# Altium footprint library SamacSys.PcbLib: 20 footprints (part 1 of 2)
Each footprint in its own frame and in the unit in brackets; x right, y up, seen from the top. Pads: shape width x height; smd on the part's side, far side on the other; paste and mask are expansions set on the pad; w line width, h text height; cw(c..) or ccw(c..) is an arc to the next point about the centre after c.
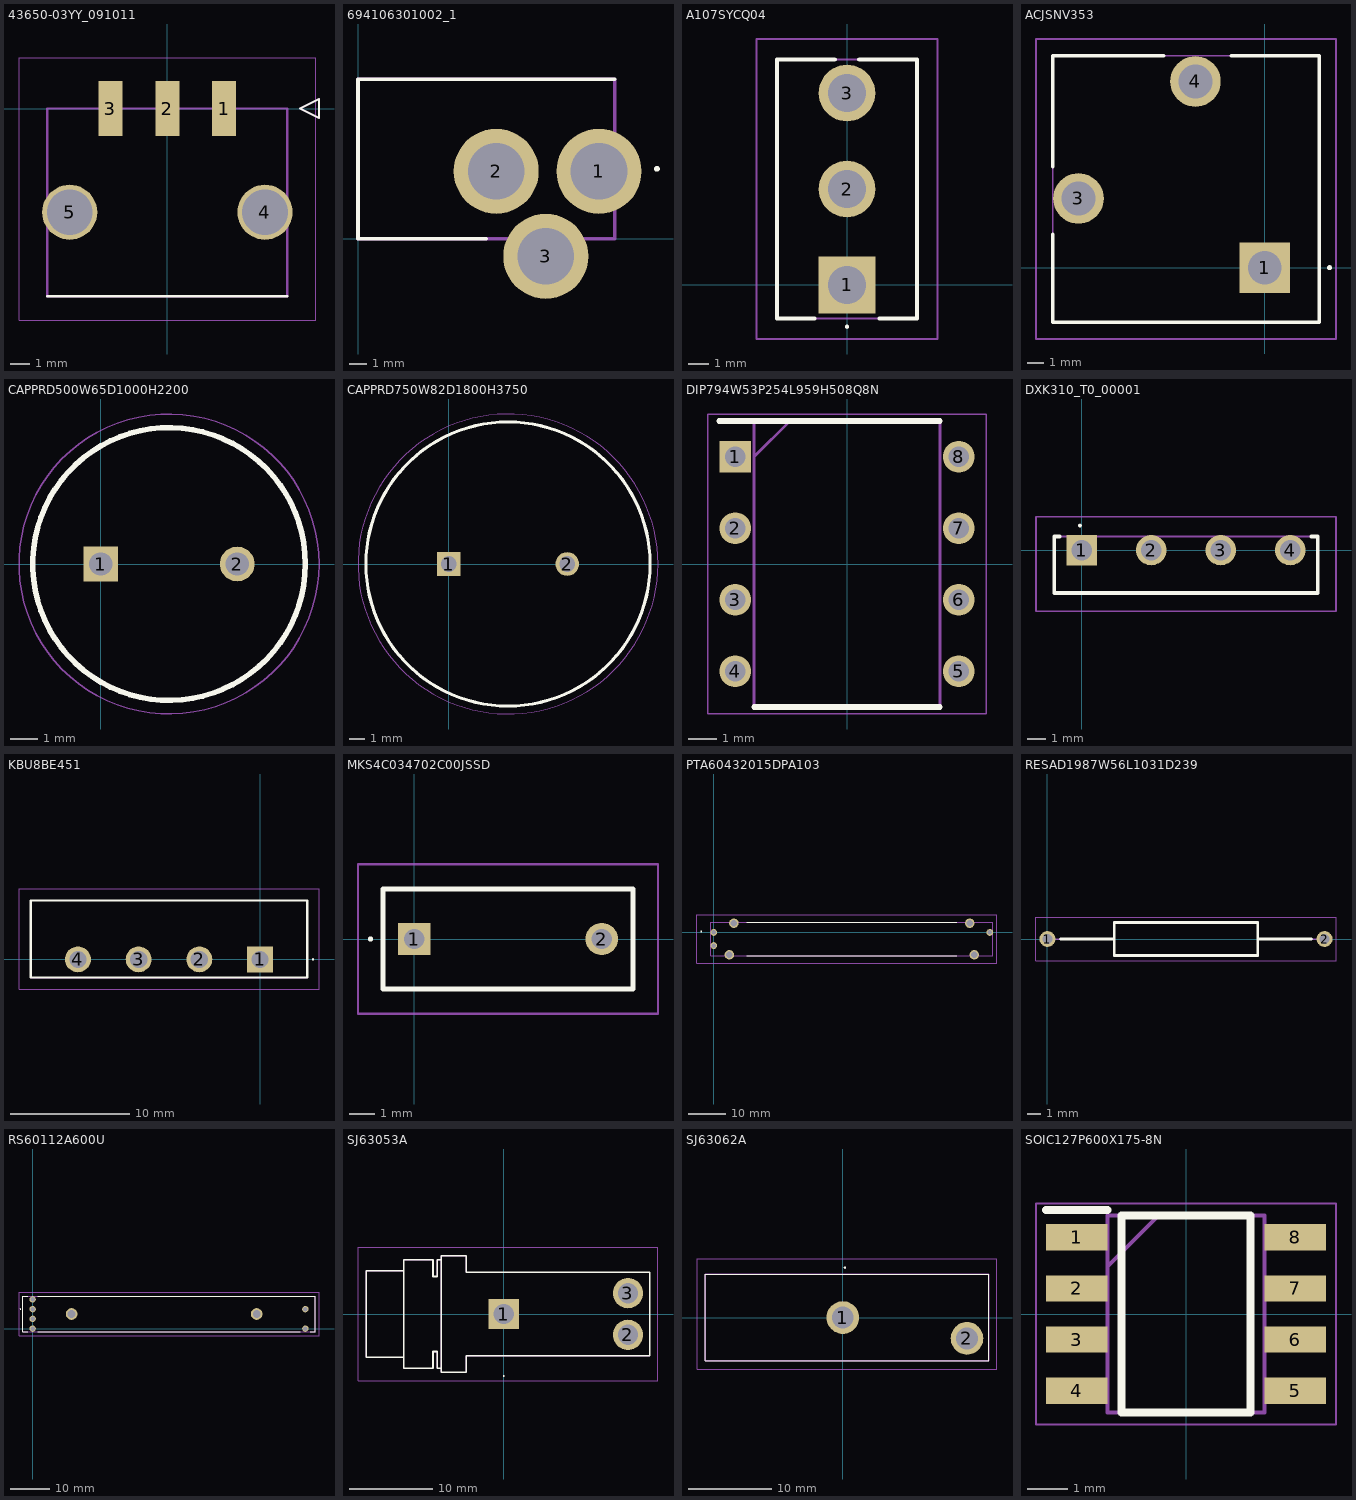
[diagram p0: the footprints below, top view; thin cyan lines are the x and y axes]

## 43650-03YY_091011 [mm]
pads (5):
  rect 1.27x2.92 smd: 1(3,0) 2(0,0) 3(-3,0)
  round 2.91 hole 2.41: 4(5.15,-5.47) 5(-5.15,-5.47)
Top Overlay:
  lines w0.127: -6.325,-9.9 6.325,-9.9 ; 7,0 8,0.5 8,-0.5 7,0
Mechanical 13:
  lines w0.127: -6.325,-9.9 -6.325,0 6.325,0 6.325,-9.9 -6.325,-9.9 ; 7,0 8,0.5 8,-0.5 7,0
Mechanical 15:
  lines w0.05: -7.824,-11.17 -7.824,2.679 7.824,2.679 7.824,-11.17 -7.824,-11.17
3D body "43650-0310.stp": height 5.71, standoff -1.9, extent -6.175,-10.06 6.475,0.678

## 694106301002_1 [mm]
pads (3):
  round 4.8 hole 3.2: 1(13.6,3.8) 2(7.8,3.8) 3(10.6,-1)
Top Overlay:
  circle w0.2: c16.867,3.939 r0.064
  lines w0.2: 7.25,0 0,0 0,9 14.5,9
Mechanical 13:
  lines w0.2: 0,0 0,9 14.5,9 14.5,0 0,0
3D body "694106301002.stp": height 11.02, standoff -3.47, extent 0.12,-1.22 14.62,8.28

## A107SYCQ04 [mil]
pads (3):
  rect 109.49x109.49 hole 73: 1(0,0)
  round 109.49 hole 73: 2(0,185) 3(0,370)
Top Overlay:
  lines w3.94: 0,-82.68 ccw(c0,-80.71) 0,-78.74 ccw(c0,-80.71) 0,-82.68
  lines w7.87: -62.99,-65 -135,-65 -135,435 -23.62,435 ; 23.62,435 135,435 135,-65 62.99,-65
Mechanical 13:
  lines w3.94: -135,-65 -135,435 135,435 135,-65 -135,-65
Mechanical 15:
  lines w3.94: -174.37,-104.37 -174.37,474.37 174.37,474.37 174.37,-104.37 -174.37,-104.37
3D body "A107SYCQ04.stp": height 1113.94, standoff -196.85, extent -135,-65 135,435

## ACJSNV353 [mm]
pads (3):
  rect 3x3 hole 2: 1(0,0)
  round 3 hole 2: 3(-11.05,4.11) 4(-4.11,11.05)
Top Overlay:
  lines w0.2: -12.57,2 -12.57,-3.23 3.23,-3.23 3.23,12.57 -2,12.57 ; -12.57,6 -12.57,12.57 -6,12.57 ; 3.8,0 ccw(c3.85,0) 3.9,0 ; 3.8,0 cw(c3.85,0) 3.9,0 ; 3.8,0 ccw(c3.85,0) 3.9,0
Mechanical 13:
  lines w0.1: -12.57,-3.23 -12.57,12.57 3.23,12.57 3.23,-3.23 -12.57,-3.23
Mechanical 15:
  lines w0.1: -13.57,-4.23 -13.57,13.57 4.23,13.57 4.23,-4.23 -13.57,-4.23
3D body "ACJS-NV35-3.stp": height 27.1, standoff -5, extent -12.57,-3.23 3.23,12.57

## CAPPRD500W65D1000H2200 [mm]
pads (2):
  rect 1.275x1.275 hole 0.85: 1(0,0)
  round 1.275 hole 0.85: 2(5,0)
Top Overlay:
  circle w0.2: c2.5,0 r5
Mechanical 13:
  circle w0.1: c2.5,0 r5
Mechanical 15:
  circle w0.05: c2.5,0 r5.5
3D body "EEU-TP1V331B.stp": height 22, standoff -10, extent -2.75,-5.238 7.75,5.238

## CAPPRD750W82D1800H3750 [mm]
pads (2):
  rect 1.5x1.5 hole 1: 1(0,0)
  round 1.5 hole 1: 2(7.5,0)
Top Overlay:
  circle w0.2: c3.75,0 r9
Mechanical 13:
  circle w0.1: c3.75,0 r9
Mechanical 15:
  circle w0.05: c3.75,0 r9.5
3D body "860020581026.stp": height 37.5, standoff -10, extent -5.5,-9.232 13,9.232

## DIP794W53P254L959H508Q8N [mm]
pads (8):
  rect 1.13x1.13 hole 0.73: 1(-3.97,3.81)
  round 1.13 hole 0.73: 2(-3.97,1.27) 3(-3.97,-1.27) 4(-3.97,-3.81) 5(3.97,-3.81) 6(3.97,-1.27) 7(3.97,1.27) 8(3.97,3.81)
Top Overlay:
  lines w0.2: -4.535,5.08 3.3,5.08 ; -3.3,-5.08 3.3,-5.08
Mechanical 13:
  lines w0.1: -3.3,3.81 -2.03,5.08 ; -3.3,-5.08 3.3,-5.08 3.3,5.08 -3.3,5.08 -3.3,-5.08
Mechanical 15:
  lines w0.05: -4.945,-5.33 4.945,-5.33 4.945,5.33 -4.945,5.33 -4.945,-5.33
3D body "TL072ACP.stp": height 4.21, standoff -3.37, extent -4.102,-4.635 4.102,4.635

## DXK310_T0_00001 [mm]
pads (4):
  rect 1.665x1.665 hole 1.11: 1(0,0)
  round 1.665 hole 1.11: 2(3.81,0) 3(7.62,0) 4(11.43,0)
Top Overlay:
  lines w0.1: -0.1,1.3 cw(c-0.1,1.35) -0.1,1.4 cw(c-0.1,1.35) -0.1,1.3
  lines w0.2: -1.2,0.75 -1.51,0.75 -1.51,-2.35 12.94,-2.35 12.94,0.75 12.6,0.75
Mechanical 13:
  lines w0.1: -1.51,-2.35 -1.51,0.75 12.94,0.75 12.94,-2.35 -1.51,-2.35
Mechanical 15:
  lines w0.1: -2.51,-3.35 -2.51,1.833 13.94,1.833 13.94,-3.35 -2.51,-3.35
3D body "DXK310_T0_00001.stp": height 12.61, standoff -11.89, extent -1.535,-2.01 12.965,1.09

## KBU8BE451 [mm]
pads (4):
  rect 2.175x2.175 hole 1.45: 1(0,0)
  round 2.175 hole 1.45: 2(-5.1,0) 3(-10.2,0) 4(-15.3,0)
Top Overlay:
  lines w0.1: 4.4,0 cw(c4.45,0) 4.5,0 cw(c4.45,0) 4.4,0
  lines w0.2: -19.25,-1.525 -19.25,4.95 3.95,4.95 3.95,-1.525 -19.25,-1.525
Mechanical 13:
  lines w0.1: -19.25,-1.525 -19.25,4.95 3.95,4.95 3.95,-1.525 -19.25,-1.525
Mechanical 15:
  lines w0.1: -20.25,-2.525 -20.25,5.95 4.95,5.95 4.95,-2.525 -20.25,-2.525
3D body "KBU8B-E4_51.stp": height 20.51, standoff -29.39, extent -19.25,-1.71 3.95,5.14

## MKS4C034702C00JSSD [mm]
pads (2):
  rect 1.3x1.3 hole 0.8: 1(0,0)
  round 1.3 hole 0.8: 2(7.5,0)
Top Overlay:
  lines w0.1: -1.8,0 ccw(c-1.75,0) -1.7,0 ccw(c-1.75,0) -1.8,0
  lines w0.2: -1.25,-2 -1.25,2 8.75,2 8.75,-2 -1.25,-2
Mechanical 13:
  lines w0.1: -1.25,-2 -1.25,2 8.75,2 8.75,-2 -1.25,-2
Mechanical 15:
  lines w0.1: -2.25,-3 -2.25,3 9.75,3 9.75,-3 -2.25,-3
3D body "MKS4C034702C00JSSD.stp": height 9.1, standoff -5, extent -1.25,-2 8.75,2

## PTA60432015DPA103 [mm]
pads (7):
  round 1.8 hole 1.2: 1(0,0) 2(0,-3.5) 3(73.5,0)
  round 2.55 hole 1.7: MH1(4.15,-5.95) MH2(5.35,2.45) MH3(69.35,-5.95) MH4(68.15,2.45)
Top Overlay:
  lines w0.1: 8.75,-6.25 64.75,-6.25 ; 8.75,2.75 64.75,2.75
  lines w0.2: -3.45,0.25 ccw(c-3.35,0.25) -3.25,0.25 ccw(c-3.35,0.25) -3.45,0.25
Mechanical 13:
  lines w0.2: -0.75,-6.25 -0.75,2.75 74.25,2.75 74.25,-6.25 -0.75,-6.25
Mechanical 15:
  lines w0.1: -4.45,-8.225 -4.45,4.725 75.4,4.725 75.4,-8.225 -4.45,-8.225
3D body "PTA6043-2015DPA103.stp": height 21.6, standoff -5, extent -0.75,-6.695 74.25,3.195

## RESAD1987W56L1031D239 [mm]
pads (2):
  round 1.15 hole 0.75: 1(0,0) 2(19.9,0)
Top Overlay:
  lines w0.2: 0.925,0 4.795,0 ; 15.105,0 18.975,0 ; 4.795,-1.195 15.105,-1.195 15.105,1.195 4.795,1.195 4.795,-1.195
Mechanical 13:
  lines w0.1: 0,0 4.795,0 ; 15.105,0 19.9,0 ; 4.795,-1.195 15.105,-1.195 15.105,1.195 4.795,1.195 4.795,-1.195
Mechanical 15:
  lines w0.05: -0.825,-1.545 20.725,-1.545 20.725,1.545 -0.825,1.545 -0.825,-1.545
3D body "RS01A1R000FE12.stp": height 3.18, standoff -3.18, extent -0.279,-1.577 20.149,1.577

## RS60112A600U [mm]
pads (8):
  round 1.65 hole 1.1: A1(0,0) A2(0,5) A3(70,0) B1(0,2.5) B2(0,7.5) B3(70,5)
  round 3 hole 2: MH1(10,3.75) MH2(57.5,3.75)
Top Overlay:
  lines w0.2: -3.2,5 ccw(c-3.15,5) -3.1,5 ; -3.2,5 cw(c-3.15,5) -3.1,5 ; -3.2,5 ccw(c-3.15,5) -3.1,5 ; -2.5,-0.75 -2.5,8.25 ; -2.5,-0.75 -2.5,8.25 ; -2.5,-0.75 -1.25,-0.75 -2.5,-0.75 ; -2.5,8.25 -1.25,8.25 -2.5,8.25 ; 72.5,-0.75 72.5,8.25 ; 72.5,-0.75 72.5,8.25 ; 72.5,-0.75 71.25,-0.75 72.5,-0.75 ; 72.5,8.25 1.25,8.25 72.5,8.25 ; 1.25,-0.75 68.75,-0.75 1.25,-0.75
Mechanical 13:
  lines w0.1: -2.5,-0.75 -2.5,8.25 72.5,8.25 72.5,-0.75 -2.5,-0.75
Mechanical 15:
  lines w0.1: -3.5,-1.825 -3.5,9.325 73.5,9.325 73.5,-1.825 -3.5,-1.825
3D body "RS60112A600U.stp": height 21.8, standoff -4, extent -2.5,-0.85 72.5,8.35

## SJ63053A [mm]
pads (3):
  rect 3.63x3.63 hole 2.42: 1(0,0)
  round 3.63 hole 2.42: 2(14.9,-2.5) 3(14.9,2.5)
Top Overlay:
  lines w0.1: 0,-7.5 ccw(c0,-7.45) 0,-7.4 ccw(c0,-7.45) 0,-7.5
  lines w0.2: -12,-5.2 -16.5,-5.2 -16.5,5.2 -12,5.2 ; -7.5,-6.5 -8,-6.5 -8,-4.5 -8.5,-4.5 -8.5,-6.5 -12,-6.5 -12,6.5 -8.5,6.5 -8.5,4.5 -8,4.5 -8,6.5 -7.5,6.5 ; -7.5,-7 -7.5,0 -7.5,7 -4.5,7 -4.5,5 17.5,5 17.5,-5 -4.5,-5 -4.5,-7 -7.5,-7
Mechanical 13:
  lines w0.1: -12,-5.2 -16.5,-5.2 -16.5,5.2 -12,5.2 ; -7.5,-6.5 -8,-6.5 -8,-4.5 -8.5,-4.5 -8.5,-6.5 -12,-6.5 -12,6.5 -8.5,6.5 -8.5,4.5 -8,4.5 -8,6.5 -7.5,6.5 ; -7.5,-7 -7.5,0 -7.5,7 -4.5,7 -4.5,5 17.5,5 17.5,-5 -4.5,-5 -4.5,-7 -7.5,-7
Mechanical 15:
  lines w0.1: -17.5,-8 -17.5,8 18.5,8 18.5,-8 -17.5,-8
3D body "SJ-63053A.stp": height 4.55, standoff -29.3, extent -6.95,-10.901 6.95,5.7

## SJ63062A [mm]
pads (2):
  round 3.93 hole 2.62: 1(0,0) 2(14.9,-2.5)
Top Overlay:
  lines w0.1: -16.5,-5.2 -16.5,5.2 17.5,5.2 17.5,-5.2 -16.5,-5.2
  lines w0.2: 0.2,6 ccw(c0.25,6) 0.3,6 ; 0.2,6 cw(c0.25,6) 0.3,6 ; 0.2,6 ccw(c0.25,6) 0.3,6
Mechanical 13:
  lines w0.2: -16.5,-5.2 -16.5,5.2 17.5,5.2 17.5,-5.2 -16.5,-5.2
Mechanical 15:
  lines w0.1: -17.5,-6.2 -17.5,7.05 18.5,7.05 18.5,-6.2 -17.5,-6.2
3D body "SJ-63062A.stp": height 12.34, standoff -4.26, extent -16.54,-7.26 17.31,6.64

## SOIC127P600X175-8N [mm]
pads (8):
  rect 1.525x0.65 smd: 1(-2.712,1.905) 2(-2.712,0.635) 3(-2.712,-0.635) 4(-2.712,-1.905) 5(2.712,-1.905) 6(2.712,-0.635) 7(2.712,0.635) 8(2.712,1.905)
Top Overlay:
  lines w0.2: -3.475,2.58 -1.95,2.58 ; -1.6,-2.45 1.6,-2.45 1.6,2.45 -1.6,2.45 -1.6,-2.45
Mechanical 13:
  lines w0.1: -1.95,1.18 -0.68,2.45 ; -1.95,-2.45 1.95,-2.45 1.95,2.45 -1.95,2.45 -1.95,-2.45
Mechanical 15:
  lines w0.05: -3.725,-2.75 3.725,-2.75 3.725,2.75 -3.725,2.75 -3.725,-2.75
3D body "NE555DR.stp": height 1.75, standoff 0, extent -3,-2.45 3,2.45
